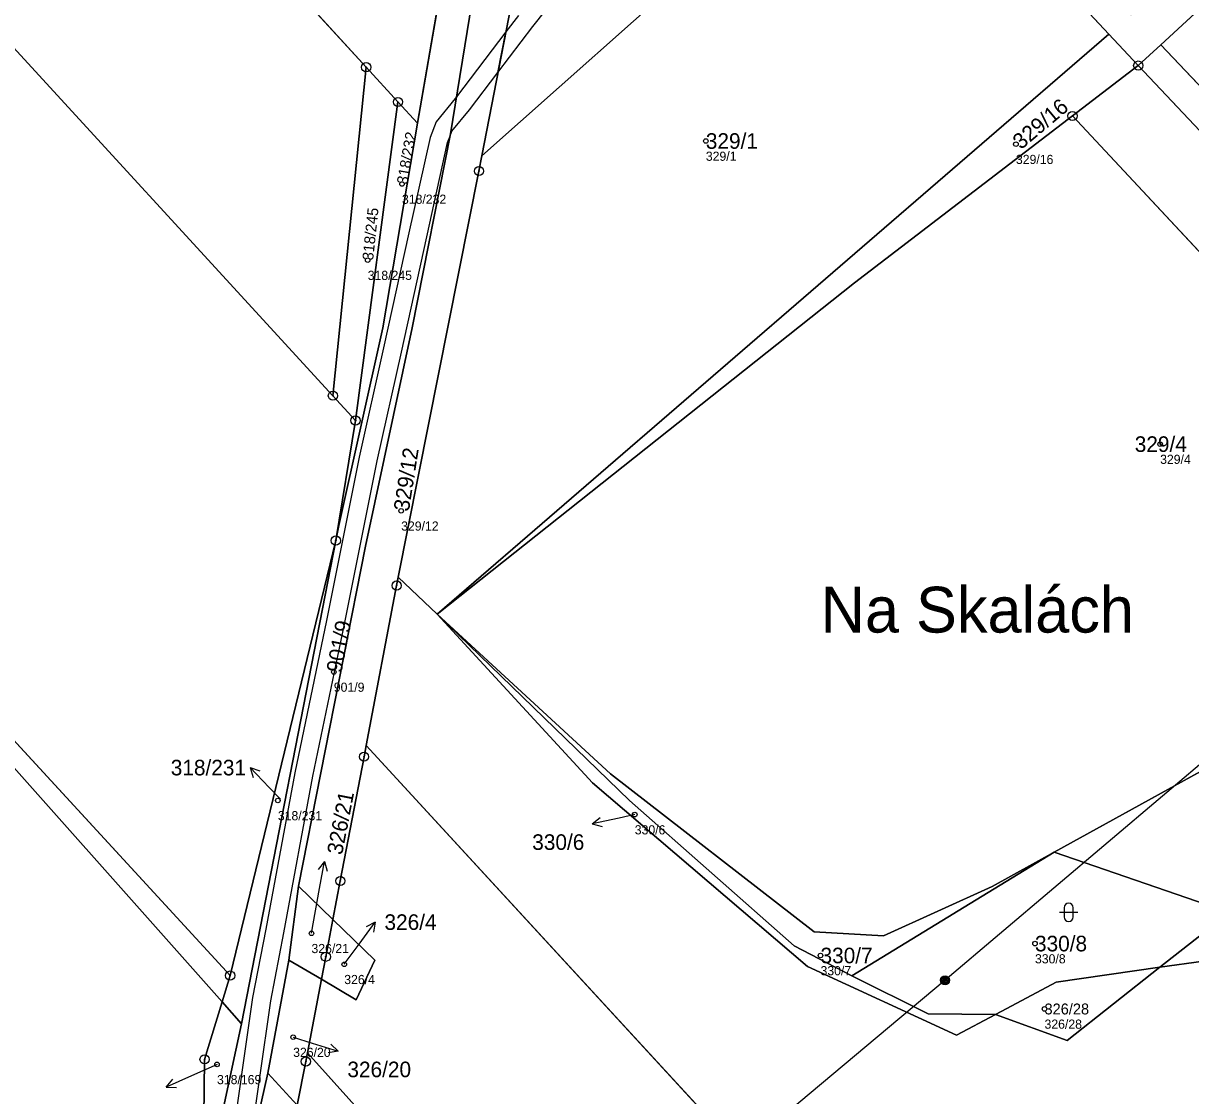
# Model space of a CAD drawing. Extents: x -734504 to -730695, y -1027923 to -1024502.
# Drawn here: x -732886.8 to -732759.3, y -1026240.6 to -1026123.7 of the extents above; entities that cross this region are included whole.
import ezdxf

# ---------------------------------------------------------------- set-up
doc = ezdxf.new("R2010")
doc.units = 0
for name, color, linetype in [('Definiční body', 7, 'Continuous'), ('Hranice parcel', 7, 'Continuous'), ('Parcelní čísla', 7, 'Continuous'), ('Polygon parcely', 7, 'Continuous'), ('Pop  PČ popisy', 7, 'Continuous'), ('Poz předměty', 7, 'Continuous'), ('Věcná břemena k části', 7, 'Continuous'), ('Značky bodu BP', 7, 'Continuous'), ('Značky kultur', 7, 'Continuous')]:
    doc.layers.add(name, color=color, linetype=linetype)

msp = doc.modelspace()

# ---------------------------------------------------------------- linework, layer by layer
at = {"layer": 'Definiční body'}
for centre in [(-732812.27, -1026136.49), (-732778.42, -1026136.84), (-732845.44, -1026141.18), (-732849.18, -1026149.49), (-732762.68, -1026169.56), (-732845.53, -1026176.84), (-732852.88, -1026194.42), (-732858.99, -1026208.44), (-732820.03, -1026209.98), (-732855.32, -1026222.93), (-732776.34, -1026224.05), (-732799.75, -1026225.35), (-732851.74, -1026226.31), (-732775.3, -1026231.18), (-732857.32, -1026234.26), (-732865.63, -1026237.23)]:
    msp.add_circle(centre, 0.25, dxfattribs=at)
at = {"layer": 'Hranice parcel'}
for p, q in [((-733002.66, -1026077.06), (-732864.2, -1026227.54)), ((-732889.48, -1026084.63), (-732849.35, -1026128.44)), ((-732762.61, -1026125.99), (-732726.91, -1026093.04)), ((-732792.46, -1026098.94), (-732768.29, -1026124.82)), ((-732843.75, -1026134.56), (-732839.46, -1026109.82)), ((-732841.59, -1026188.1), (-732768.29, -1026124.82)), ((-732765.07, -1026128.26), (-732768.29, -1026124.82)), ((-732765.07, -1026128.26), (-732762.61, -1026125.99)), ((-732731.33, -1026158.95), (-732762.61, -1026125.99)), ((-732852.98, -1026164.28), (-732849.35, -1026128.44)), ((-732849.35, -1026128.44), (-732845.88, -1026132.23)), ((-732772.25, -1026133.76), (-732765.07, -1026128.26)), ((-732716.73, -1026179.47), (-732765.07, -1026128.26)), ((-732845.88, -1026132.23), (-732850.51, -1026166.98)), ((-732845.88, -1026132.23), (-732843.75, -1026134.56)), ((-732724.65, -1026184.7), (-732772.25, -1026133.76)), ((-732850.51, -1026166.98), (-732852.98, -1026164.28)), ((-732852.66, -1026180.08), (-732850.51, -1026166.98)), ((-732864.2, -1026227.54), (-732852.66, -1026180.08)), ((-732852.66, -1026180.08), (-732862.96, -1026232.8)), ((-732841.59, -1026188.1), (-732845.84, -1026184.08)), ((-732849.35, -1026202.43), (-732773.19, -1026285.19)), ((-732774.23, -1026214.09), (-732756.15, -1026204.1)), ((-732796.33, -1026227.56), (-732774.23, -1026214.09)), ((-732774.23, -1026214.09), (-732740.84, -1026225.57)), ((-732857.79, -1026225.86), (-732856.74, -1026217.78)), ((-732852.97, -1026221.43), (-732856.74, -1026217.78)), ((-732860.1, -1026238.19), (-732857.79, -1026225.86)), ((-732854.22, -1026227.95), (-732857.79, -1026225.86)), ((-732762.7, -1026226.64), (-732774.03, -1026228.26)), ((-732865.07, -1026230.42), (-732864.2, -1026227.54)), ((-732855.75, -1026235.96), (-732854.22, -1026227.95)), ((-732862.96, -1026232.8), (-732865.07, -1026230.42)), ((-732780.66, -1026231.79), (-732784.89, -1026234.04)), ((-732867.16, -1026252.39), (-732862.96, -1026232.8)), ((-732798.14, -1026300.02), (-732855.75, -1026235.96)), ((-732856.88, -1026241.69), (-732860.1, -1026238.19))]:
    msp.add_line(p, q, dxfattribs=at)
for points in [[(-732852.98, -1026164.28), (-732893.53, -1026120.09), (-732930.17, -1026080.16), (-732965.96, -1026041.15)], [(-732865.07, -1026230.42), (-732924.57, -1026163.58), (-732955.32, -1026130.09), (-733004.06, -1026078.42)], [(-732792.46, -1026098.94), (-732811.74, -1026115.88), (-732836.72, -1026138.11)], [(-732836.72, -1026138.11), (-732831.39, -1026110.62), (-732830.98, -1026108.09)], [(-732856.74, -1026217.78), (-732849.43, -1026180.69), (-732844.31, -1026156.89), (-732840.15, -1026135.7), (-732835.73, -1026108.66)], [(-732841.59, -1026188.1), (-732796.04, -1026151.98), (-732772.25, -1026133.76)], [(-732843.75, -1026134.56), (-732847.53, -1026156.89), (-732852.34, -1026178.44), (-732852.66, -1026180.08)], [(-732845.84, -1026184.08), (-732837.04, -1026139.77), (-732836.72, -1026138.11)], [(-732849.35, -1026202.43), (-732846.02, -1026184.99), (-732845.84, -1026184.08)], [(-732796.33, -1026227.56), (-732802.62, -1026224.29), (-732820.62, -1026208.45), (-732841.59, -1026188.1)], [(-732784.89, -1026234.04), (-732801.16, -1026226.56), (-732824.63, -1026206.52), (-732841.59, -1026188.1)], [(-732841.59, -1026188.1), (-732822.67, -1026205.53), (-732800.45, -1026222.77), (-732792.86, -1026223.2), (-732781.03, -1026217.84), (-732774.23, -1026214.09)], [(-732852.97, -1026221.43), (-732852.17, -1026217.22), (-732849.58, -1026203.66), (-732849.35, -1026202.43)], [(-732733.9, -1026219.38), (-732729.06, -1026223.21), (-732743.79, -1026226.79), (-732757.95, -1026225.96), (-732762.7, -1026226.64)], [(-732852.97, -1026221.43), (-732853.75, -1026225.49), (-732854.22, -1026227.95)], [(-732854.22, -1026227.95), (-732850.44, -1026230.17), (-732848.4, -1026225.87), (-732852.97, -1026221.43)], [(-732762.7, -1026226.64), (-732757.17, -1026222.29), (-732740.84, -1026225.57)], [(-732762.7, -1026226.64), (-732772.84, -1026234.61), (-732780.66, -1026231.79)], [(-732780.66, -1026231.79), (-732788.01, -1026231.7), (-732796.33, -1026227.56)], [(-732774.03, -1026228.26), (-732779.4, -1026231.12), (-732780.66, -1026231.79)], [(-732867.16, -1026252.39), (-732866.99, -1026236.68), (-732865.07, -1026230.42)], [(-732856.88, -1026241.69), (-732855.93, -1026236.92), (-732855.75, -1026235.96)], [(-732866.25, -1026285.82), (-732864.68, -1026270.55), (-732861.54, -1026244.66), (-732860.1, -1026238.19)]]:
    msp.add_lwpolyline(points, dxfattribs=at)
at = {"layer": 'Polygon parcely'}
for points in [[(-732849.35, -1026128.44), (-732889.48, -1026084.63), (-732903.71, -1026069.26), (-732912.18, -1026060.01), (-732929.21, -1026041.1), (-732946.07, -1026022.27), (-732946.56, -1026021.8), (-732953.65, -1026028.87), (-732965.96, -1026041.15), (-732930.17, -1026080.16), (-732893.53, -1026120.09), (-732852.98, -1026164.28)], [(-732625.57, -1026057.36), (-732651.99, -1026022.72), (-732720.08, -1026085.99), (-732726.91, -1026093.04), (-732762.61, -1026125.99), (-732731.33, -1026158.95)], [(-732852.98, -1026164.28), (-732893.53, -1026120.09), (-732930.17, -1026080.16), (-732965.96, -1026041.15), (-732972.36, -1026047.53), (-733002.66, -1026077.06), (-732864.2, -1026227.54), (-732852.66, -1026180.08), (-732850.51, -1026166.98)], [(-732839.46, -1026109.82), (-732840.98, -1026107.64), (-732841.37, -1026107.07), (-732841.86, -1026106.52), (-732852.1, -1026095), (-732863.32, -1026082.37), (-732873.92, -1026070.43), (-732889.48, -1026084.63), (-732849.35, -1026128.44), (-732845.88, -1026132.23), (-732843.75, -1026134.56)], [(-732864.2, -1026227.54), (-733002.66, -1026077.06), (-733004.06, -1026078.42), (-732955.32, -1026130.09), (-732924.57, -1026163.58), (-732865.07, -1026230.42)], [(-733041.46, -1026158.65), (-733029.77, -1026195.63), (-733027.44, -1026230.97), (-733008.6, -1026245.26), (-732990.75, -1026264.28), (-732955.28, -1026303.27), (-732939.47, -1026318.33), (-732934.84, -1026323.1), (-732911.41, -1026348.06), (-732875.87, -1026318.69), (-732875.46, -1026316.43), (-732874.49, -1026311.04), (-732870.12, -1026286.75), (-732868.75, -1026268.75), (-732867.16, -1026252.39), (-732866.99, -1026236.68), (-732865.07, -1026230.42), (-732924.57, -1026163.58), (-732955.32, -1026130.09), (-733004.06, -1026078.42), (-733060.29, -1026129.03)], [(-732802.87, -1026087.8), (-732804.9, -1026085), (-732830.98, -1026108.09), (-732831.39, -1026110.62), (-732836.72, -1026138.11), (-732811.74, -1026115.88), (-732792.46, -1026098.94)], [(-732765.07, -1026128.26), (-732762.61, -1026125.99), (-732726.91, -1026093.04), (-732730.85, -1026089.34), (-732765.86, -1026122.72), (-732790.28, -1026097.02), (-732799.08, -1026087.76), (-732800.76, -1026085.99), (-732802.87, -1026087.8), (-732792.46, -1026098.94), (-732768.29, -1026124.82)], [(-732768.29, -1026124.82), (-732792.46, -1026098.94), (-732811.74, -1026115.88), (-732836.72, -1026138.11), (-732837.04, -1026139.77), (-732845.84, -1026184.08), (-732841.59, -1026188.1)], [(-732830.98, -1026108.09), (-732830.42, -1026104.59), (-732835.73, -1026108.66), (-732840.15, -1026135.7), (-732844.31, -1026156.89), (-732849.43, -1026180.69), (-732856.74, -1026217.78), (-732852.97, -1026221.43), (-732852.17, -1026217.22), (-732849.58, -1026203.66), (-732849.35, -1026202.43), (-732846.02, -1026184.99), (-732845.84, -1026184.08), (-732837.04, -1026139.77), (-732836.72, -1026138.11), (-732831.39, -1026110.62)], [(-732840.15, -1026135.7), (-732835.73, -1026108.66), (-732839.46, -1026109.82), (-732843.75, -1026134.56), (-732847.53, -1026156.89), (-732852.34, -1026178.44), (-732852.66, -1026180.08), (-732862.96, -1026232.8), (-732867.16, -1026252.39), (-732868.75, -1026268.75), (-732870.12, -1026286.75), (-732866.25, -1026285.82), (-732864.68, -1026270.55), (-732861.54, -1026244.66), (-732860.1, -1026238.19), (-732857.79, -1026225.86), (-732856.74, -1026217.78), (-732849.43, -1026180.69), (-732844.31, -1026156.89)], [(-732768.29, -1026124.82), (-732841.59, -1026188.1), (-732796.04, -1026151.98), (-732772.25, -1026133.76), (-732765.07, -1026128.26)], [(-732731.33, -1026158.95), (-732762.61, -1026125.99), (-732765.07, -1026128.26), (-732716.73, -1026179.47), (-732713.9, -1026177.23)], [(-732852.98, -1026164.28), (-732850.51, -1026166.98), (-732845.88, -1026132.23), (-732849.35, -1026128.44)], [(-732765.07, -1026128.26), (-732772.25, -1026133.76), (-732724.65, -1026184.7), (-732718.77, -1026181.08), (-732716.73, -1026179.47)], [(-732850.51, -1026166.98), (-732852.66, -1026180.08), (-732852.34, -1026178.44), (-732847.53, -1026156.89), (-732843.75, -1026134.56), (-732845.88, -1026132.23)], [(-732724.65, -1026184.7), (-732772.25, -1026133.76), (-732796.04, -1026151.98), (-732841.59, -1026188.1), (-732822.67, -1026205.53), (-732800.45, -1026222.77), (-732792.86, -1026223.2), (-732781.03, -1026217.84), (-732774.23, -1026214.09), (-732756.15, -1026204.1), (-732743.18, -1026196.11)], [(-732852.66, -1026180.08), (-732864.2, -1026227.54), (-732865.07, -1026230.42), (-732862.96, -1026232.8)], [(-732796.33, -1026227.56), (-732802.62, -1026224.29), (-732820.62, -1026208.45), (-732841.59, -1026188.1), (-732824.63, -1026206.52), (-732801.16, -1026226.56), (-732784.89, -1026234.04), (-732780.66, -1026231.79), (-732788.01, -1026231.7)], [(-732774.23, -1026214.09), (-732781.03, -1026217.84), (-732792.86, -1026223.2), (-732800.45, -1026222.77), (-732822.67, -1026205.53), (-732841.59, -1026188.1), (-732820.62, -1026208.45), (-732802.62, -1026224.29), (-732796.33, -1026227.56)], [(-732852.97, -1026221.43), (-732848.4, -1026225.87), (-732850.44, -1026230.17), (-732854.22, -1026227.95), (-732855.75, -1026235.96), (-732798.14, -1026300.02), (-732792.01, -1026302.31), (-732788.39, -1026300.59), (-732773.19, -1026285.19), (-732849.35, -1026202.43), (-732849.58, -1026203.66), (-732852.17, -1026217.22)], [(-732740.81, -1026213.9), (-732756.15, -1026204.1), (-732774.23, -1026214.09), (-732740.84, -1026225.57), (-732733.9, -1026219.38)], [(-732757.17, -1026222.29), (-732740.84, -1026225.57), (-732774.23, -1026214.09), (-732796.33, -1026227.56), (-732788.01, -1026231.7), (-732780.66, -1026231.79), (-732779.4, -1026231.12), (-732774.03, -1026228.26), (-732762.7, -1026226.64)], [(-732852.97, -1026221.43), (-732856.74, -1026217.78), (-732857.79, -1026225.86), (-732854.22, -1026227.95), (-732853.75, -1026225.49)], [(-732762.7, -1026226.64), (-732757.95, -1026225.96), (-732743.79, -1026226.79), (-732729.06, -1026223.21), (-732733.9, -1026219.38), (-732740.84, -1026225.57), (-732757.17, -1026222.29)], [(-732850.44, -1026230.17), (-732848.4, -1026225.87), (-732852.97, -1026221.43), (-732853.75, -1026225.49), (-732854.22, -1026227.95)], [(-732854.22, -1026227.95), (-732857.79, -1026225.86), (-732860.1, -1026238.19), (-732856.88, -1026241.69), (-732855.93, -1026236.92), (-732855.75, -1026235.96)], [(-732779.4, -1026231.12), (-732780.66, -1026231.79), (-732772.84, -1026234.61), (-732762.7, -1026226.64), (-732774.03, -1026228.26)], [(-732862.96, -1026232.8), (-732865.07, -1026230.42), (-732866.99, -1026236.68), (-732867.16, -1026252.39)], [(-732798.14, -1026300.02), (-732855.75, -1026235.96), (-732855.93, -1026236.92), (-732856.88, -1026241.69), (-732834.68, -1026265.81), (-732818.38, -1026284.2), (-732803.92, -1026297.85)], [(-732866.25, -1026285.82), (-732866.17, -1026288.51), (-732858.32, -1026248.95), (-732856.88, -1026241.69), (-732860.1, -1026238.19), (-732861.54, -1026244.66), (-732864.68, -1026270.55)]]:
    msp.add_lwpolyline(points, close=True, dxfattribs=at)
msp.add_lwpolyline([(-732757.95, -1026225.96), (-732762.7, -1026226.64), (-732772.84, -1026234.61), (-732780.66, -1026231.79), (-732784.89, -1026234.04), (-732801.16, -1026226.56), (-732824.63, -1026206.52), (-732841.59, -1026188.1), (-732845.84, -1026184.08), (-732846.02, -1026184.99), (-732849.35, -1026202.43), (-732773.19, -1026285.19)], dxfattribs=at)
at = {"layer": 'Pop  PČ popisy'}
for p, q in [((-732859.92, -1026207.01), (-732862.01, -1026204.85)), ((-732862.01, -1026204.85), (-732860.95, -1026205.22)), ((-732862.01, -1026204.85), (-732861.67, -1026205.92)), ((-732858.69, -1026208.28), (-732859.92, -1026207.01)), ((-732824.68, -1026210.98), (-732823.8, -1026210.29)), ((-732821.74, -1026210.36), (-732824.68, -1026210.98)), ((-732820.03, -1026209.98), (-732821.74, -1026210.36)), ((-732824.68, -1026210.98), (-732823.59, -1026211.27)), ((-732853.91, -1026215.09), (-732854.58, -1026215.98)), ((-732854.43, -1026218.04), (-732853.91, -1026215.09)), ((-732853.91, -1026215.09), (-732853.59, -1026216.16)), ((-732855.32, -1026222.93), (-732854.43, -1026218.04)), ((-732850.13, -1026224.13), (-732848.37, -1026221.7)), ((-732848.37, -1026221.7), (-732849.36, -1026222.22)), ((-732848.37, -1026221.7), (-732848.55, -1026222.81)), ((-732851.74, -1026226.31), (-732850.13, -1026224.13)), ((-732857.32, -1026234.26), (-732855.26, -1026234.9)), ((-732855.26, -1026234.9), (-732852.39, -1026235.78)), ((-732852.39, -1026235.78), (-732853.49, -1026235.96)), ((-732852.39, -1026235.78), (-732853.2, -1026235.01)), ((-732865.63, -1026237.23), (-732868.43, -1026238.48)), ((-732868.43, -1026238.48), (-732871.17, -1026239.7)), ((-732871.17, -1026239.7), (-732870.46, -1026238.84)), ((-732871.17, -1026239.7), (-732870.05, -1026239.75))]:
    msp.add_line(p, q, dxfattribs=at)
at = {"layer": 'Poz předměty'}
for p, q in [((-732722.83, -1026174.41), (-732786.16, -1026228.06)), ((-732786.16, -1026228.06), (-732845.31, -1026277.58))]:
    msp.add_line(p, q, dxfattribs=at)
for radius in [0.5, 0.4, 0.3, 0.2, 0.1]:
    msp.add_circle((-732786.16, -1026228.06), radius, dxfattribs=at)
at = {"layer": 'Věcná břemena k části'}
for points in [[(-732832.72, -1026122.78), (-732834.1, -1026124.59), (-732834.96, -1026129.01), (-732831.14, -1026124), (-732826.62, -1026118.24)], [(-732862.16, -1026247.04), (-732859.76, -1026230.29), (-732858.34, -1026222.87), (-732855.16, -1026205.8), (-732851.72, -1026189.21), (-732848.16, -1026171.4), (-732845.49, -1026159.51), (-732842.73, -1026146.96), (-732840.46, -1026136.67), (-732840.22, -1026136.04), (-732839.98, -1026135.43), (-732838.07, -1026133.1), (-732834.96, -1026129.01), (-732834.1, -1026124.59), (-732839.49, -1026131.68), (-732839.63, -1026131.86), (-732841.72, -1026134.41), (-732842.38, -1026136.09), (-732844.69, -1026146.52), (-732847.45, -1026159.07), (-732850.12, -1026170.98), (-732853.68, -1026188.81), (-732857.12, -1026205.42), (-732860.3, -1026222.49), (-732861.74, -1026229.95), (-732864.14, -1026246.76)]]:
    msp.add_lwpolyline(points, dxfattribs=at)
at = {"layer": 'Značky bodu BP'}
for centre, radius in [((-732849.35, -1026128.44), 0.5), ((-732849.35, -1026128.44), 0.0303), ((-732765.07, -1026128.26), 0.5), ((-732765.07, -1026128.26), 0.0303), ((-732845.88, -1026132.23), 0.5), ((-732845.88, -1026132.23), 0.0303), ((-732772.25, -1026133.76), 0.5), ((-732772.25, -1026133.76), 0.0303), ((-732837.04, -1026139.77), 0.5), ((-732837.04, -1026139.77), 0.0303), ((-732852.98, -1026164.28), 0.5), ((-732852.98, -1026164.28), 0.0303), ((-732850.51, -1026166.98), 0.5), ((-732850.51, -1026166.98), 0.0303), ((-732852.66, -1026180.08), 0.5), ((-732852.66, -1026180.08), 0.0303), ((-732846.02, -1026184.99), 0.5), ((-732846.02, -1026184.99), 0.0303), ((-732849.58, -1026203.66), 0.5), ((-732849.58, -1026203.66), 0.0303), ((-732852.17, -1026217.22), 0.5), ((-732852.17, -1026217.22), 0.0303), ((-732853.75, -1026225.49), 0.5), ((-732853.75, -1026225.49), 0.0303), ((-732864.2, -1026227.54), 0.5), ((-732864.2, -1026227.54), 0.0303), ((-732866.99, -1026236.68), 0.5), ((-732866.99, -1026236.68), 0.0303), ((-732855.93, -1026236.92), 0.5), ((-732855.93, -1026236.92), 0.0303)]:
    msp.add_circle(centre, radius, dxfattribs=at)
at = {"layer": 'Značky kultur'}
for p, q in [((-732773.66, -1026220.64), (-732771.66, -1026220.64)), ((-732773.16, -1026220.14), (-732773.16, -1026221.14)), ((-732772.16, -1026221.14), (-732772.16, -1026220.14))]:
    msp.add_line(p, q, dxfattribs=at)
for centre, start, end in [((-732772.66, -1026220.14), 0, 180), ((-732772.66, -1026221.14), 180, 359.9879)]:
    msp.add_arc(centre, 0.5, start, end, dxfattribs=at)

# ---------------------------------------------------------------- texts
at = {"layer": 'Definiční body'}
for s, p in [('329/1', (-732812.27, -1026138.65)), ('329/16', (-732778.42, -1026139)), ('318/232', (-732845.44, -1026143.34)), ('318/245', (-732849.18, -1026151.65)), ('329/4', (-732762.68, -1026171.72)), ('329/12', (-732845.53, -1026179)), ('901/9', (-732852.88, -1026196.58)), ('318/231', (-732858.99, -1026210.6)), ('330/6', (-732820.03, -1026212.14)), ('326/21', (-732855.32, -1026225.09)), ('330/8', (-732776.34, -1026226.21)), ('330/7', (-732799.75, -1026227.51)), ('326/4', (-732851.74, -1026228.47)), ('326/28', (-732775.3, -1026233.34)), ('326/20', (-732857.32, -1026236.42)), ('318/169', (-732865.63, -1026239.39))]:
    msp.add_text(s, height=1, dxfattribs=at).set_placement(p)
at = {"layer": 'Parcelní čísla'}
for s, height, rotation, p in [('329/16', 1.7, 40, (-732777.87, -1026137.49)), ('318/232', 1.19, 80, (-732844.85, -1026141.28)), ('318/245', 1.19, 84, (-732848.59, -1026149.55)), ('329/12', 1.7, 81, (-732844.69, -1026176.97)), ('901/9', 1.7, 79, (-732852.05, -1026194.58)), ('326/21', 1.7, 79, (-732851.98, -1026214.45))]:
    msp.add_text(s, height=height, rotation=rotation, dxfattribs=at).set_placement(p)
for s, height, p in [('329/1', 1.7, (-732812.27, -1026137.34)), ('329/4', 1.7, (-732765.45, -1026170.41)), ('318/231', 1.7, (-732870.68, -1026205.7)), ('330/6', 1.7, (-732831.22, -1026213.83)), ('326/4', 1.7, (-732847.35, -1026222.56)), ('330/8', 1.7, (-732776.34, -1026224.9)), ('330/7', 1.7, (-732799.75, -1026226.2)), ('326/28', 1.19, (-732775.3, -1026231.78)), ('326/20', 1.7, (-732851.4, -1026238.63))]:
    msp.add_text(s, height=height, dxfattribs=at).set_placement(p)
at = {"layer": 'Pop  PČ popisy'}
msp.add_text('Na Skalách', height=5, dxfattribs=at).set_placement((-732799.73, -1026190.12))

doc.saveas('drawing.dxf')
